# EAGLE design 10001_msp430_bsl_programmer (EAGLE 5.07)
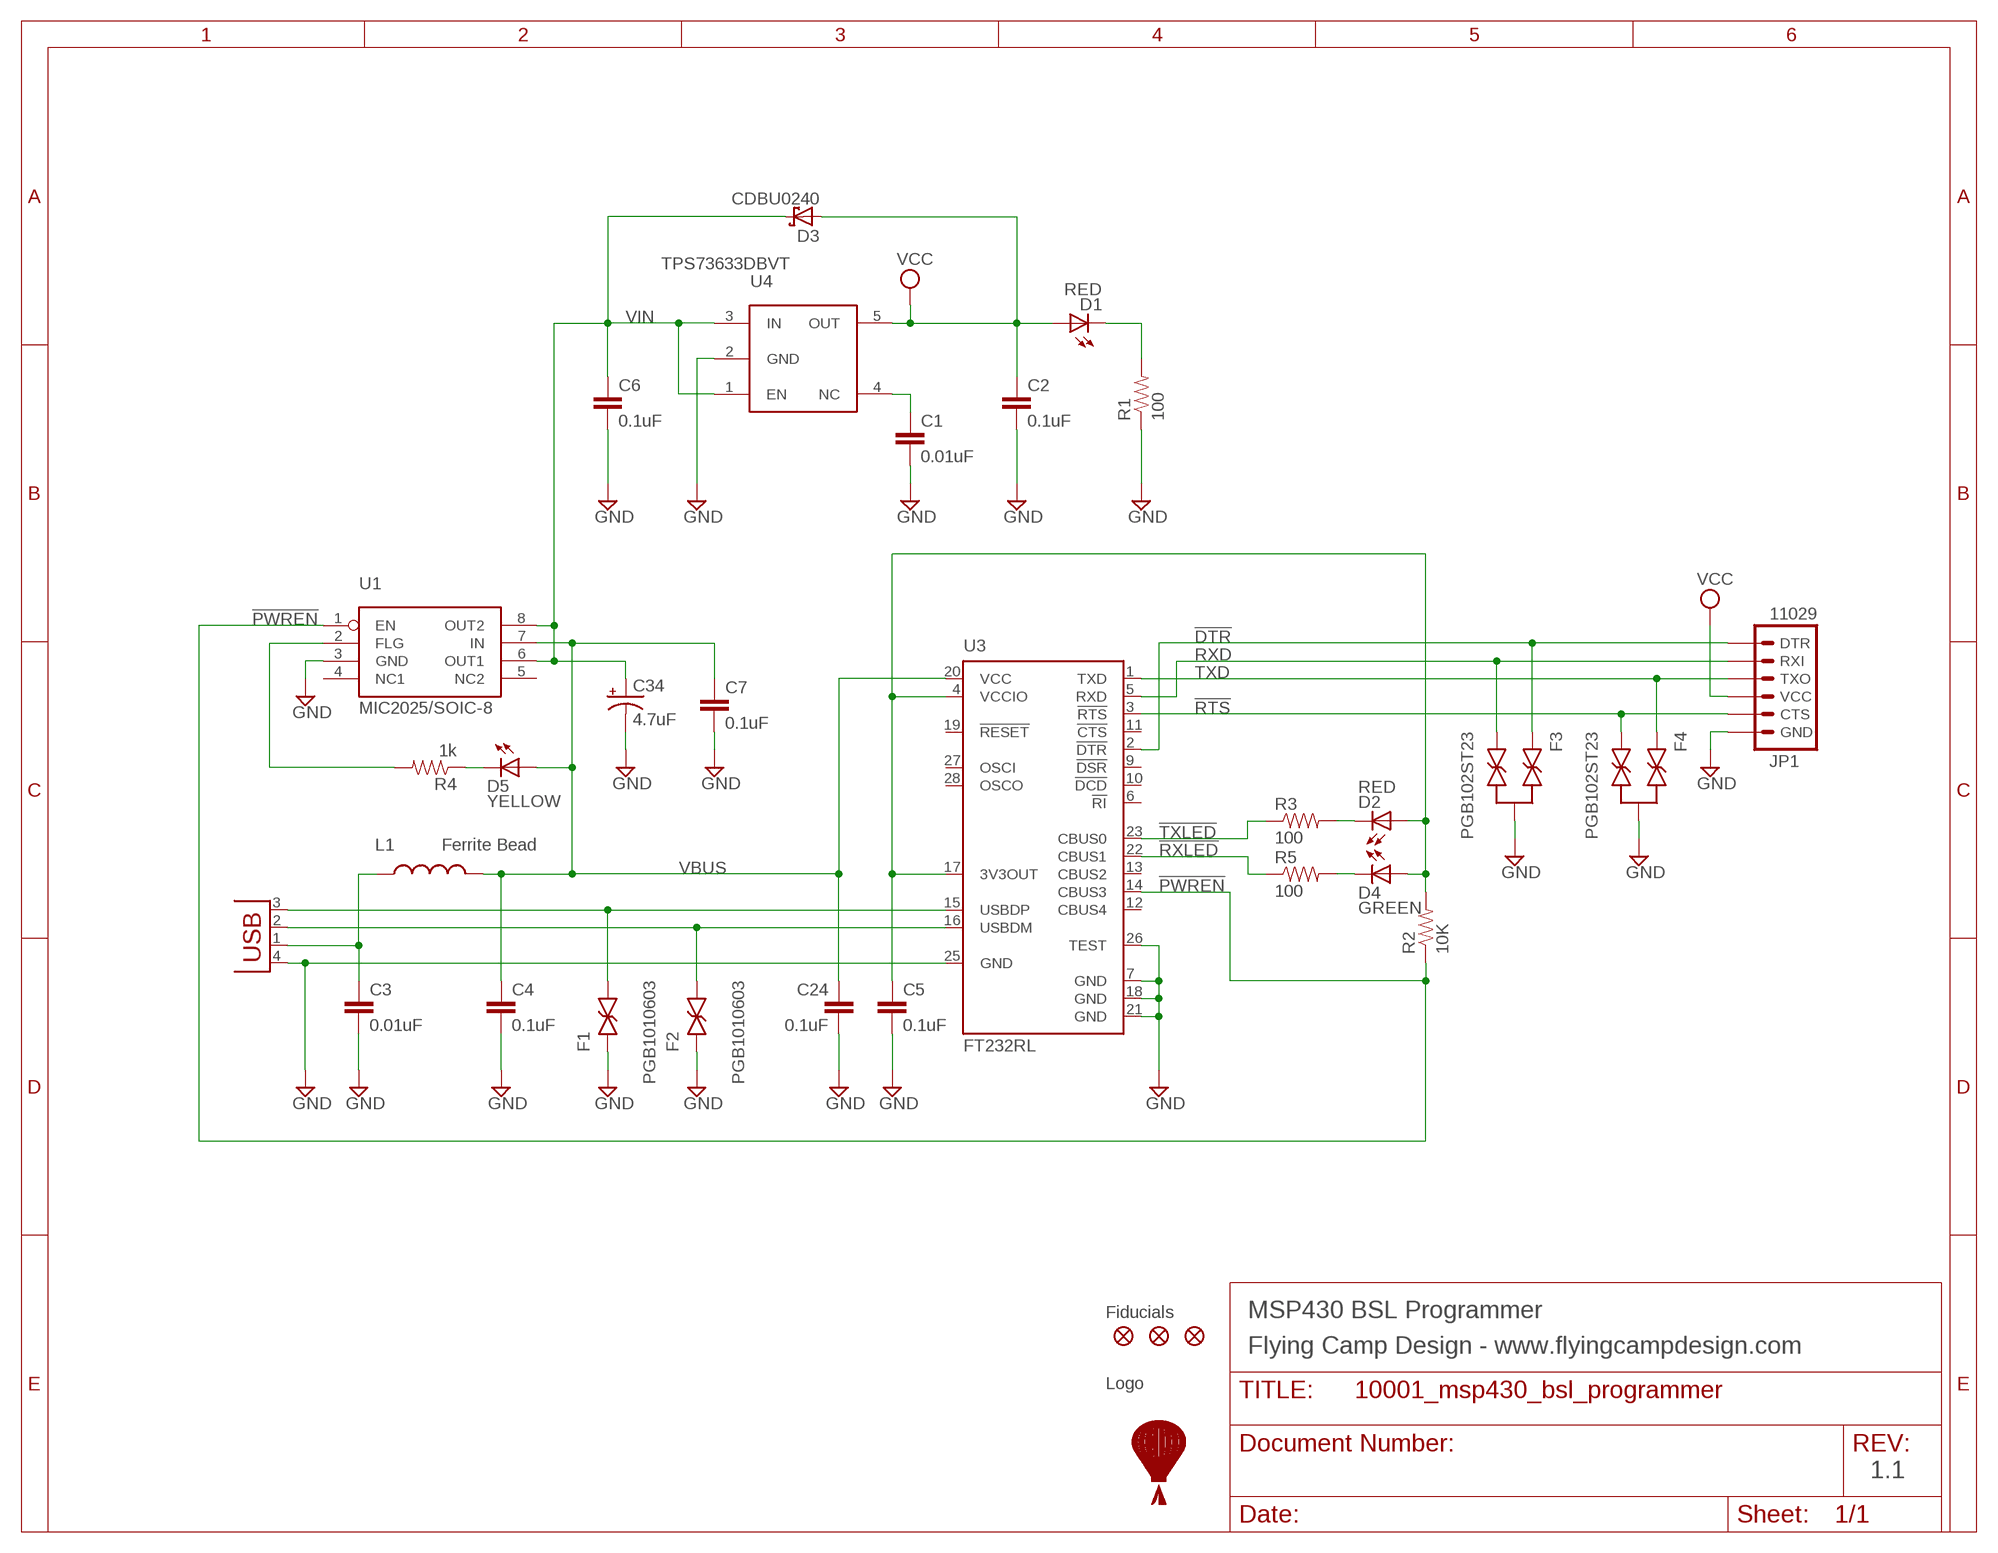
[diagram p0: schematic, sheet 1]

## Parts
C1  0.01uF  CAPACITOR1608  [CAPC1608]
C2  0.1uF  CAPACITOR1608  [CAPC1608]
C3  0.01uF  CAPACITOR1608  [CAPC1608]
C4  0.1uF  CAPACITOR1608  [CAPC1608]
C5  0.1uF  CAPACITOR1608  [CAPC1608]
C6  0.1uF  CAPACITOR1608  [CAPC1608]
C7  0.1uF  CAPACITOR1608  [CAPC1608]
C24  0.1uF  CAPACITOR1608  [CAPC1608]
C34  4.7uF  CAP_POL1206  [EIA3216]
D1  RED  LED1608  [LEDC1608]
D2  RED  LED1608  [LEDC1608]
D3  CDBU0240  SCHOTTKY-DIODE0603  [D0603]
D4  GREEN  LED1608  [LEDC1608]
D5  YELLOW  LED1608  [LEDC1608]
F1  PGB1010603  LITTELFUSE_PGB1010603  [CAPC1608]
F2  PGB1010603  LITTELFUSE_PGB1010603  [CAPC1608]
F3  PGB102ST23  LITTELFUSE_PGB102ST23  [SOT23]
F4  PGB102ST23  LITTELFUSE_PGB102ST23  [SOT23]
JP1  11029  ARDUINO_SERIAL_PROGRAMSMD  [1X06-SMD]
L1  Ferrite Bead  INDUCTOR0603  [0603]
P1  MOLEX_48037-1000  [MOLEX_48037-1000]
R1  100  RESISTOR1608  [RESC1608]
R2  10K  RESISTOR1608  [RESC1608]
R3  100  RESISTOR1608  [RESC1608]
R4  1k  RESISTOR1608  [RESC1608]
R5  100  RESISTOR1608  [RESC1608]
U1  MIC2025/SOIC-8  [SOIC-8]
U3  FT232RL  [SSOP28]
U4  TPS73633DBVT  MIC5235SOT95P280-5  [SOT95P280-5]
U$1  FLYING_CAMP_DESIGN_LOGO  [FLYING_CAMP_DESIGN_LOGO]
U$2  FIDUCIAL1X2  [FIDUCIAL-1X2]
U$3  FIDUCIAL1X2  [FIDUCIAL-1X2]
U$4  FIDUCIAL1X2  [FIDUCIAL-1X2]

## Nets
!DTR: F3.1 JP1.1(DTR) U3.2(!DTR)
!PWREN: R2.1 U1.1(EN) U3.14(CBUS3)
!RTS: F4.2 JP1.5(CTS) U3.3(!RTS)
!RXLED: R5.1 U3.22(CBUS1)
!TXLED: R3.1 U3.23(CBUS0)
D+: F1.2 P1.3(D+) U3.15(USBDP)
D-: F2.2 P1.2(D-) U3.16(USBDM)
GND [power]: C1.2 C2.2 C3.2 C4.2 C5.2 C6.2 C7.2 C24.2 C34.C(-) F1.1 F2.1 F3.3 F4.3 JP1.6(GND) P1.4(GND) R1.1 U1.3(GND) U3.7(GND) U3.18(GND) U3.21(GND) U3.25(GND) U3.26(TEST) U4.2(GND)
N$1: D1.C R1.2
N$2: C1.1 U4.4(NC)
N$3: R4.2 U1.2(FLG)
N$4: D5.C R4.1
N$34: D2.C R3.2
N$35: D4.C R5.2
RXD: F3.2 JP1.2(RXI) U3.5(RXD)
TXD: F4.1 JP1.3(TXO) U3.1(TXD)
VBUS: C4.1 C7.1 C24.1 D5.A L1.2 U1.7(IN) U3.20(VCC)
VCC: C2.1 D1.A D3.A JP1.4(VCC) U4.5(OUT)
VCCIO: C5.1 D2.A D4.A R2.2 U3.4(VCCIO) U3.17(3V3OUT)
VIN: C6.1 C34.A(+) D3.C U1.6(OUT1) U1.8(OUT2) U4.1(EN) U4.3(IN)
VUSB: C3.1 L1.1 P1.1(VBUS)
Unconnected: U1.4(NC1) U1.5(NC2) U3.6(!RI) U3.9(!DSR) U3.10(!DCD) U3.11(!CTS) U3.12(CBUS4) U3.13(CBUS2) U3.19(!RESET) U3.27(OSCI) U3.28(OSCO)

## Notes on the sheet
- Fiducials | MSP430 BSL Programmer
- Flying Camp Design - www.flyingcampdesign.com
- Logo
- 1.1

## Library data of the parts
C1-C7 C24 = cwilson:CAPACITOR: Capacitor
C34 = SparkFun:CAP_POL: Capacitor Polarized
D1 D2 D4 D5 = cwilson:LED: LED
D3 = cwilson-old:SCHOTTKY-DIODE: Schottky Diode
F1 F2 = cwilson:LITTELFUSE_PGB1010603
F3 F4 = cwilson-old:LITTELFUSE_PGB102ST23
JP1 = SparkFun:ARDUINO_SERIAL_PROGRAM
L1 = SparkFun:INDUCTOR: Inductors
P1 = cwilson-old:MOLEX_48037-1000
R1-R5 = cwilson:RESISTOR: Resistor
U1 = cwilson-old:MIC2025
U3 = cwilson-old:FT232R: Source: http://www.ftdichip.com/Documents/DataSheets/DS_FT232R_v104.pdf
U4 = cwilson:MIC5235
U$1 = flying_camp_design:FLYING_CAMP_DESIGN_LOGO
U$2-U$4 = SparkFun:FIDUCIAL: Fiducial Alignment Points

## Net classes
1 power: width 0.635 mm, clearance 0.406 mm

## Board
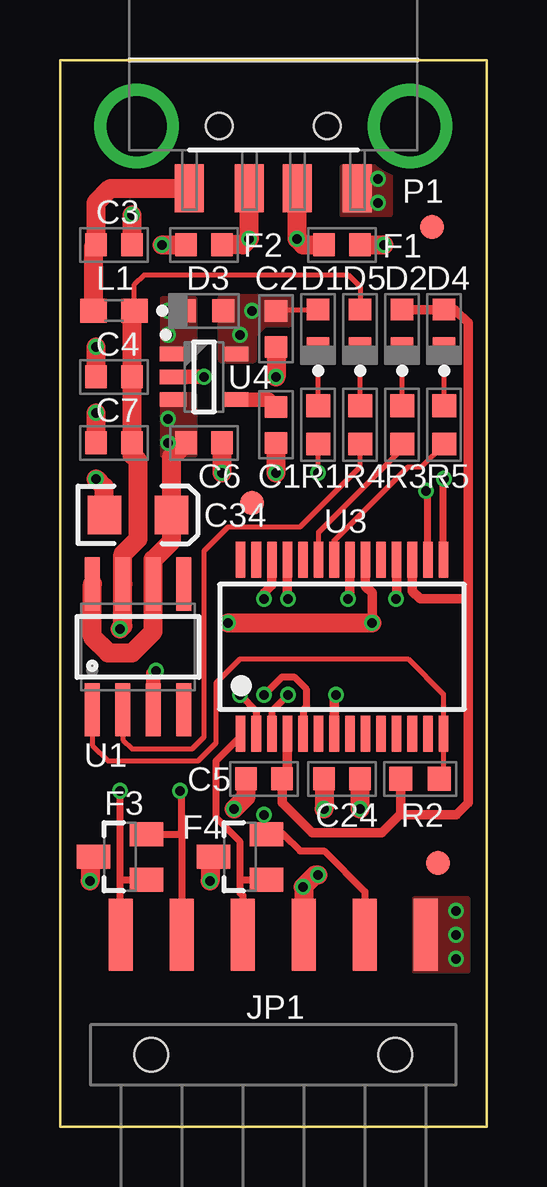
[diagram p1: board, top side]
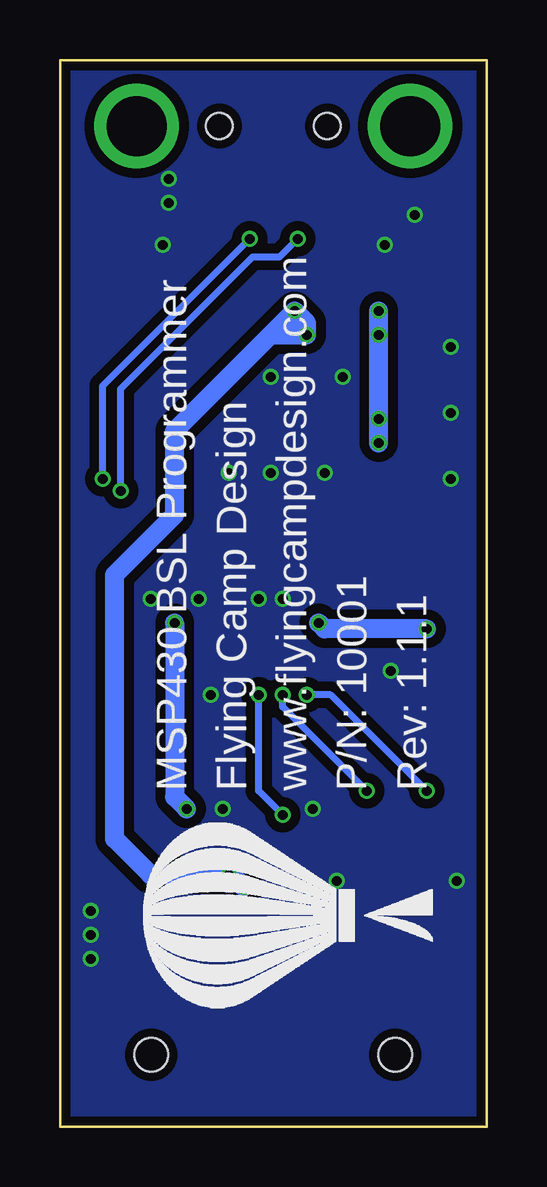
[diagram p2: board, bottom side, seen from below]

Size 17.78 x 44.45 mm. Coordinates in mm from the lower left corner, seen from the top.
Outline: 0,0 0,44.45 17.78,44.45 17.78,0 0,0
Copper layers (1*16): Top 0.0356mm / dielectric 1.5062mm / Bottom 0.0356mm
Design rules "33each": minimum track width 6mil, minimum drill 15mil, track to track 6mil, track to pad 6mil, pad to pad 6mil, via to via 6mil, smd to smd 6mil, copper to edge 15mil, drill to drill 0mil, minimum pad ring 7mil, minimum via ring 5mil, stop-mask expansion 2.5mil, vias tented up to drill 20mil, thermal gap 10mil

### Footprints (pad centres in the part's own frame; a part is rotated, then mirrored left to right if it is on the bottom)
CAPC1608 = smd 0.9 x 0.95: 1 -0.75,0; 2 0.75,0
EIA3216 = smd 1.4 x 1.6: A 1.4,0; C -1.4,0
LEDC1608 = smd 0.9 x 0.95: A 0.8,0; C -0.8,0
D0603 = smd 0.9 x 0.95: A 0.8,0; C -0.8,0
SOT23 = smd 1 x 1.4: 1 -0.95,-1.1; 2 0.95,-1.1; 3 0,1.1
1X06-SMD = smd 1 x 3: 1 -6.35,5; 2 -3.81,5; 3 -1.27,5; 4 1.27,5; 5 3.81,5; 6 6.35,5 | hole 1.4: -5.08,0; 5.08,0
0603 = smd 1.1 x 1: 1 -0.85,0; 2 0.85,0
MOLEX_48037-1000 = smd 1.2 x 2: 1 3.5,2.6; 2 1,2.6; 3 -1,2.6; 4 -3.5,2.6 | drill 2.5 pad 3.5 round: 5 5.7,0; 6 -5.7,0 | hole 1.1: -2.25,0; 2.25,0
RESC1608 = smd 0.95 x 1: 1 -0.8,0; 2 0.8,0
SOIC-8 = smd 0.61 x 2.21: 1 -1.905,-2.616; 2 -0.635,-2.616; 3 0.635,-2.616; 4 1.905,-2.616; 5 1.905,2.616; 6 0.635,2.616; 7 -0.635,2.616; 8 -1.905,2.616
SSOP28 = smd 0.4 x 1.5: 1 -4.225,-3.625; 2 -3.575,-3.625; 3 -2.925,-3.625; 4 -2.275,-3.625; 5 -1.625,-3.625; 6 -0.975,-3.625; 7 -0.325,-3.625; 8 0.325,-3.625; 9 0.975,-3.625; 10 1.625,-3.625; 11 2.275,-3.625; 12 2.925,-3.625; 13 3.575,-3.625; 14 4.225,-3.625; 15 4.225,3.625; 16 3.575,3.625; 17 2.925,3.625; 18 2.275,3.625; 19 1.625,3.625; 20 0.975,3.625; 21 0.325,3.625; 22 -0.325,3.625; 23 -0.975,3.625; 24 -1.625,3.625; 25 -2.275,3.625; 26 -2.925,3.625; 27 -3.575,3.625; 28 -4.225,3.625
SOT95P280-5 = smd 1.1 x 0.6: 1 -1.3,0.95; 2 -1.3,0; 3 -1.3,-0.95; 4 1.3,-0.95; 5 1.3,0.95
FIDUCIAL-1X2 = smd 1 x 1: 1 0,0

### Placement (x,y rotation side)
C1  9,29.25 270 top
C2  9,33.25 270 top
C3  2.25,36.75 0 top
C4  2.25,31.25 180 top
C5  8.5,14.5 180 top
C6  6,28.5 0 top
C7  2.25,28.5 180 top
C24  11.75,14.5 180 top
C34  3.25,25.5 0 top
D1  10.75,33.25 90 top
D2  14.25,33.25 90 top
D3  6,34 0 top
D4  16,33.25 90 top
D5  12.5,33.25 90 top
F1  11.75,36.75 180 top
F2  6,36.75 0 top
F3  2.5,11.25 90 top
F4  7.5,11.25 90 top
JP1  8.89,3 0 top
L1  2.25,34 0 top
P1  8.89,41.7 180 top
R1  10.75,29.25 90 top
R2  15,14.5 180 top
R3  14.25,29.25 90 top
R4  12.5,29.25 270 top
R5  16,29.25 90 top
U1  3.25,20 0 top
U3  11.75,20 0 top
U4  6,31.25 0 top
U$1  0.92,3.74 90 bottom
U$2  8,26 0 top
U$3  15.5,37.5 0 top
U$4  15.75,11 0 top

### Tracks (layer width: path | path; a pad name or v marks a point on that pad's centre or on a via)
!DTR  (via drill 0.4)
  Top 0.2: 2.5,8 JP1.1 | 2.5,10.25 2.55,10.3
  Top 0.3: 2.5,8 2.5,10.25 v2.5,14 | U3.2 8.18,17.32 v7.5,18 | 2.55,10.3 F3.1
  Bottom 0.3: v7.5,18 6.5,18 v2.5,14
!PWREN
  Top 0.1: 15.97,14.82 15.97,14.97 16,15 16,14.75 15.8,14.55 R2.1
  Top 0.2: R2.1 15.97,14.68 15.97,14.82 U3.14 15.97,18.02 14.5,19.5 7.5,19.5 6.5,18.5 6.5,16 5.75,15.25 2,15.25 1.34,15.9 U1.1
!RTS  (via drill 0.4)
  Top 0.2: F4.2 8.5,12.3
  Top 0.3: U3.3 8.82,17.32 v9.5,18 | JP1.5 12.7,9.8 11,11.5 10,11.5 9.3,12.2 F4.2 | 8.5,12.3 v8.5,13
  Bottom 0.3: v9.5,18 9.5,14 v8.5,13
!RXLED
  Top 0.2: R5.1 15.05,27.5 14.5,27.5 11.43,24.43 U3.22
!TXLED
  Top 0.2: U3.23 10.78,24.77 14.25,28.25 R3.1
D+  (via drill 0.4)
  Top 0.3: U3.15 15.97,26.98 v16,27
  Top 0.8: P1.3 9.89,37.02 v9.88,37 10.12,36.75 F1.2
  Bottom 0.3: v16,27 16,30.88 v9.88,37
D-  (via drill 0.4)
  Top 0.3: U3.16 15.32,26.43 v15.25,26.5
  Top 0.8: F2.2 7.62,36.75 v7.88,37 7.89,37.02 P1.2
  Bottom 0.3: v7.88,37 8.62,36.25 9.75,36.25 15.25,30.75 v15.25,26.5
GND  (via drill 0.4)
  Top 0.2: v10.75,27.25 R1.1
  Top 0.4: U3.25 9.47,22.02 v9.5,22 | U3.21 12.07,22.07 v12,22 | U3.18 14.03,22.02 v14,22 | U3.7 11.43,17.93 v11.5,18 | U3.26 8.82,22.57 8.5,22.25 v8.5,22
  Top 0.6: U4.2 v6,31.25 | U1.3 3.88,18.89 v4,19
  Top 0.8: C2.2 v9,31.25 | v9,27.25 C1.2 | C3.2 v3,38 | C4.2 v1.5,32.5 | C7.2 v1.5,29.75 | v6.75,27.25 C6.2 | C24.2 v11,13.25 | C5.2 7.75,13.75 v7.25,13.25 | v1.25,10.25 1.25,11.1 F3.3 | v6.25,10.25 6.25,11.1 F4.3 | v4.25,36.75 F2.1 | F1.1 v13.5,36.75 | C34.C 1.85,26.65 v1.5,27
  other vias: 13.25,39.5 16.5,9 16.5,7 13.25,38.5 16.5,8
  pour Bottom (isolate 0.25): 17.78,44.45 17.78,0 0,0 0,44.45
  pour Top (no thermals): 14.75,9.5 14.75,6.5 17,6.5 17,9.5
  pour Top (no thermals): 11.75,40 13.75,40 13.75,38 11.75,38
N$1
  Top 0.2: R1.2 D1.C
N$2
  Top 0.6: U4.4 8.7,30.3 C1.1
N$3
  Top 0.2: R4.2 12.5,27.5 10,25 7,25 6,24 6,16.25 5.5,15.75 3,15.75 2.62,16.14 U1.2
N$4
  Top 0.2: R4.1 D5.C
N$34
  Top 0.2: R3.2 D2.C
N$35
  Top 0.2: R5.2 D4.C
RXD  (via drill 0.4)
  Top 0.2: 5.03,12.2 5.08,12.25
  Top 0.3: JP1.2 5.08,12.25 5.08,13.92 v5,14 | F3.2 5.03,12.2 | v8.5,18 9.25,18.75 9.75,18.75 10.25,18.25 10.25,17.5 10.12,17.38 U3.5
  Bottom 0.3: v8.5,18 8.5,17.5 v5,14
TXD
  Top 0.2: 7.53,16.27 U3.1 | 7.5,10.25 7.55,10.3
  Top 0.3: 7.53,16.27 6.5,15.25 6.5,12.88 7.5,11.88 7.5,10.25 7.5,9.75 7.62,9.63 JP1.3 | 7.55,10.3 F4.1
VBUS  (via drill 0.4)
  Top 0.2: 3.1,34.1 L1.2 3.1,35.1 3.5,35.5 12,35.5 12.5,35 D5.A
  Top 0.4: U3.20 12.72,22.52 13,22.25 v13,21
  Top 0.6: 3,33.9 L1.2
  Top 0.8: v12.5,13.25 C24.1 | v2.5,20.75 2.62,20.86 U1.7 2.62,23.86 3.25,24.5 3.25,27.75 3,28 C7.1 C4.1 3,33.9 | v7,21 v13,21
  Bottom 0.8: v2.5,20.75 6.75,20.75 v7,21 | v13,21 13,13.75 v12.5,13.25
VCC  (via drill 0.4)
  Top 0.2: 9.05,34.05 D1.A
  Top 0.4: C2.1 9.05,34.05
  Top 0.8: v10.75,10.5 10.62,10.5 v10.12,10 10.16,9.96 JP1.4
  Bottom 0.8: 7.5,33.5 v7.5,33 9,33 | 7.5,33.5 v8,34 8.5,33.5 | 9,33 13,29 13,25.5 15.5,23 15.5,12 14,10.5 v10.75,10.5 10.62,10.5 v10.12,10 | 9,33 8.5,33.5 | 8.5,33.5 7.5,33.5
  pour Top (no thermals): 6.75,34.5 9.5,34.5 9.5,33.5 8.5,33.5 8,33 8,32 6.75,32
VCCIO
  Top 0.2: 14.2,13.05 14.25,13 | C5.1 9.47,14.72
  Top 0.4: 17,22 17,33.5 16.45,34.05 D4.A D2.A | U3.17 14.68,22.32 15,22 17,22 | 17,22 17,13.5 16.5,13 14.25,13 | R2.2 14.2,13.05 13.4,12.25 10.5,12.25 9.25,13.5 C5.1 | 9.47,14.72 U3.4
VIN  (via drill 0.4)
  Top 0.8: U1.8 1.34,20.41 2,19.75 3,19.75 3.88,20.64 U1.6 3.88,23.64 4.65,24.4 C34.A 4.65,27.9 C6.1
  Bottom 0.8: v4.5,28.5 v4.5,34
  other vias: 4.5,33 4.5,29.5
  pour Top (no thermals): 4.25,34.5 4.25,32 5.62,32 5.62,34.5
  pour Top (no thermals): 5.62,30.5 4.25,30.5 4.25,28 5.62,28
VUSB
  Top 0.8: L1.1 1.4,36.65 C3.1 1.5,38.5 2.1,39.1 P1.1

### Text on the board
bPlace: Rev: 1.1.1 | P/N: 10001 | www.flyingcampdesign.com | Flying Camp Design | MSP430 BSL Programmer
tNames: JP1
